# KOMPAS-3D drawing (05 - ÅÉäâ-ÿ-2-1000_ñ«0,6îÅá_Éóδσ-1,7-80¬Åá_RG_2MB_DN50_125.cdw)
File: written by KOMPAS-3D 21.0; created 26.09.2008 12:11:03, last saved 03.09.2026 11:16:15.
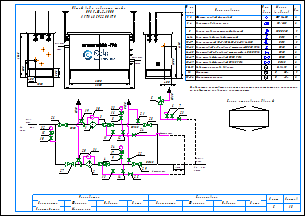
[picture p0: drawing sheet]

Sheets 1-2: A3, landscape

Document properties: Наименование: Макро:21; Автор: RaskoAdmin; Форматы листов документа: 2xA3; Полное имя файла: \\UR38nt01\Departments\КТО\КБ ПУРДГ\Заявки\Прайс-лист на типовые шкафы ГРПШ\ПРДГ_стандарт_20_03_2026\ПРДГ с RG_2MB\ПРДГ-Ш-2-1000_до0,6МПа_Рвых-1,7-80кПа_RG_2MB_DN50_125.cdw

Title block, sheet 1: Наименование: Пункт учета газа / ПУГ-Ш-400-Р / ЛГТИ.485922.001ТУ; designation: ЛГТИ.03.4411141; sheet number: 1; Количество листов документа: 2; organisation: ООО "ЭЛЬСТЕР Газэлектроника"; Форматы листов документа: A3; stored path: C:\Рабочие документы\Компас\ПУГ\Схема.cdw; Разработал: Устинов; Проверил: Кошкин; Утвердил: Кошкин
Title block, sheet 2: sheet number: 2; stored path: D:\Рабочие документы\Заявки\ПУРДГ\ПУРДГ-ШУЭО-2-100-Р 4411220.cdw; designation, second copy: ЛГТИ.03.4411141-

Views: Вид 1, Вид 2
Referenced files: wcvoit.frw
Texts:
  Normal
  Вход
  газа
  PDI
  Выход
  Р=     кПа
  DN125
  DN50
  DN20
  Импульс DN20
  ≥5DN
  HYSWLongFangSong
  № на
  схеме
  Усл.
  обозн.
  Марка
  (модель)
  Кол.
  Фильтр газовый фланцевый
  ФГ 16-50
  Регулятор давления газа
  RG/2MB
  Клапан предохранительный сбросной
  КПС DN20
  Кран шаровой газовый латунный
  DN15
  Кран кнопочный VE-РАСКО-НЗ-1,6-G1/2-М20
  Кран шаровой "под приварку" штуцерный DN20 PN16
  Кран шаровой "под приварку" штуцерный п/п DN20 PN16
  Кран шаровой фланцевый DN50 PN16
  Кран шаровой фланцевый DN125 PN16
  Индикатор перепада давления
  Delta 15
  Манометр
  Манометр-напоромер
  0...     МПа
  0...     кПа
  Общий вид и габариты шкафа
  ПРДГ-Ш-2-1000
  Выход газа
  Вход газа
  Схема открывания дверей
  Р=        МПа
  logo-rasko-ge.png
  Предприятие изготовитель может заменять комплектующие на аналогичные,
  не ухудшающие заявленных характеристик.
  Должность
  Конструктор
  Фамилия
  Подпись
  Дата
  Согласовано
  Максимкин
  Лист
  Листов
  POLYLINE_STYLE_0.18_RGB_0_0_0
  POLYLINE_STYLE_0.50_RGB_0_0_0
  POLYLINE_STYLE_0.34_RGB_0_0_0
  PHANTOM_RGB_0_0_0_SC_1_THICK_0.18
  K5LT_THIN_RGB_0_0_0_THICK_0.18
  K5LT32769_RGB_0_0_0_THICK_0.18
  K5LT12_RGB_0_0_0_SC_1_THICK_0.18
  K5LT_DASHED_RGB_0_0_0_SC_1_THICK_0.18
  ACISOTGL_RGB_0_0_0_SC_0.8_THICK_0.25
  CONTINUOUS_RGB_0_127_31_THICK_0.3
  CONTINUOUS_RGB_0_0_255_THICK_0.35
  CONTINUOUS_RGB_255_0_0_THICK_0.35
  POLYLINE_STYLE_0.25_RGB_0_0_0
  CONTINUOUS_RGB_0_0_0_THICK_0.5
  POLYLINE_STYLE_0.35_RGB_0_0_255
  CONTINUOUS_RGB_0_0_0_THICK_0.4
  CONTINUOUS_RGB_0_0_0_THICK_0.35
  Без оформления
Dimensions and other numbers on the sheet: 1; 2; 3; 4; 5; 10; 27; 28; 29; 23; 8; 12; 19; 20; 21; 22; 25; 24; 30; 31; 15; 16; 26; 6; 7; 11; 14; 13; 33; 1, 2; 3, 4; 6-14; 9; 15-17; 18-23; 24-25; 26-27; 28-29; 30-31; 32; 33-34; 400; 1050; 500; 305; 2500; 1565; 2800; 17; 34; 1000; 4130; 18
